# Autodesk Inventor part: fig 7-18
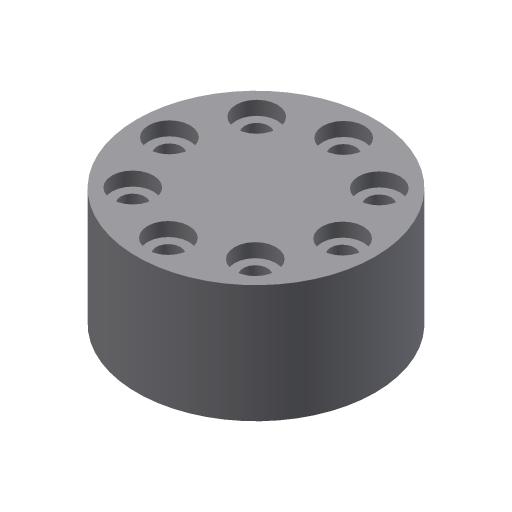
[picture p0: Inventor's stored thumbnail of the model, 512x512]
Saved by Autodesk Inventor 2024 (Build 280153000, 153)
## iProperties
Created: 2004-05
Part Number: fig 7-18
Document SubType Name: Modeling
Designer: CADCIM Technologies
Manufacturer: Standard
Standards Organization: Custom
Density: 1 g/cm^3
Material: Generic
Appearance: Default
Author: CADCIM Technologies
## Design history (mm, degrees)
sketch "Sketch1"
  geometry: C1 r 17.175 at (0, 0)
  constraints: 1 centre point
extrude "Extrusion1" new body sketch "Sketch1" distance "d0" = 17; taper "d1" = 0 deg
sketch "Sketch2"
  geometry: 1 further point
hole "Hole1" sketch "Sketch2" at (12.571, -0.074) diameter "d2" = 3.5; stored, may be unused: countersink angle "d6" = 90 deg, drill point angle "d8" = 118 deg; dims "d3" = 6, "d4" = 6, "d5" = 2, "d7" = 8
pattern_circular "Circular Pattern1" dims angle "d11" = 360 deg
body "Solid1"
